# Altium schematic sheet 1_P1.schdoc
size 429 x 307 mm; Symbol: Drawing-Symbol_A4; Device: Drawing-Symbol_A4; Company: 嘉立创EDA; Version: V1.0; Page Size: A4; @Project Name: Dual_Motor_Driver_V3.1; @Page Count: 1; @Update Date: 2025-08-30; @Create Date: 2025-08-30; @Schematic Name: Motor_Driver; @Page No: 1; @Page Name: P1; @Create Time: 14:29:45; @Update Time: 15:29:46; Width: 1655; Height: 1170; Region Start: 1; X Region Count: 6; Y Region Count: 4; Blade Width: 10; Title Block Position: 3
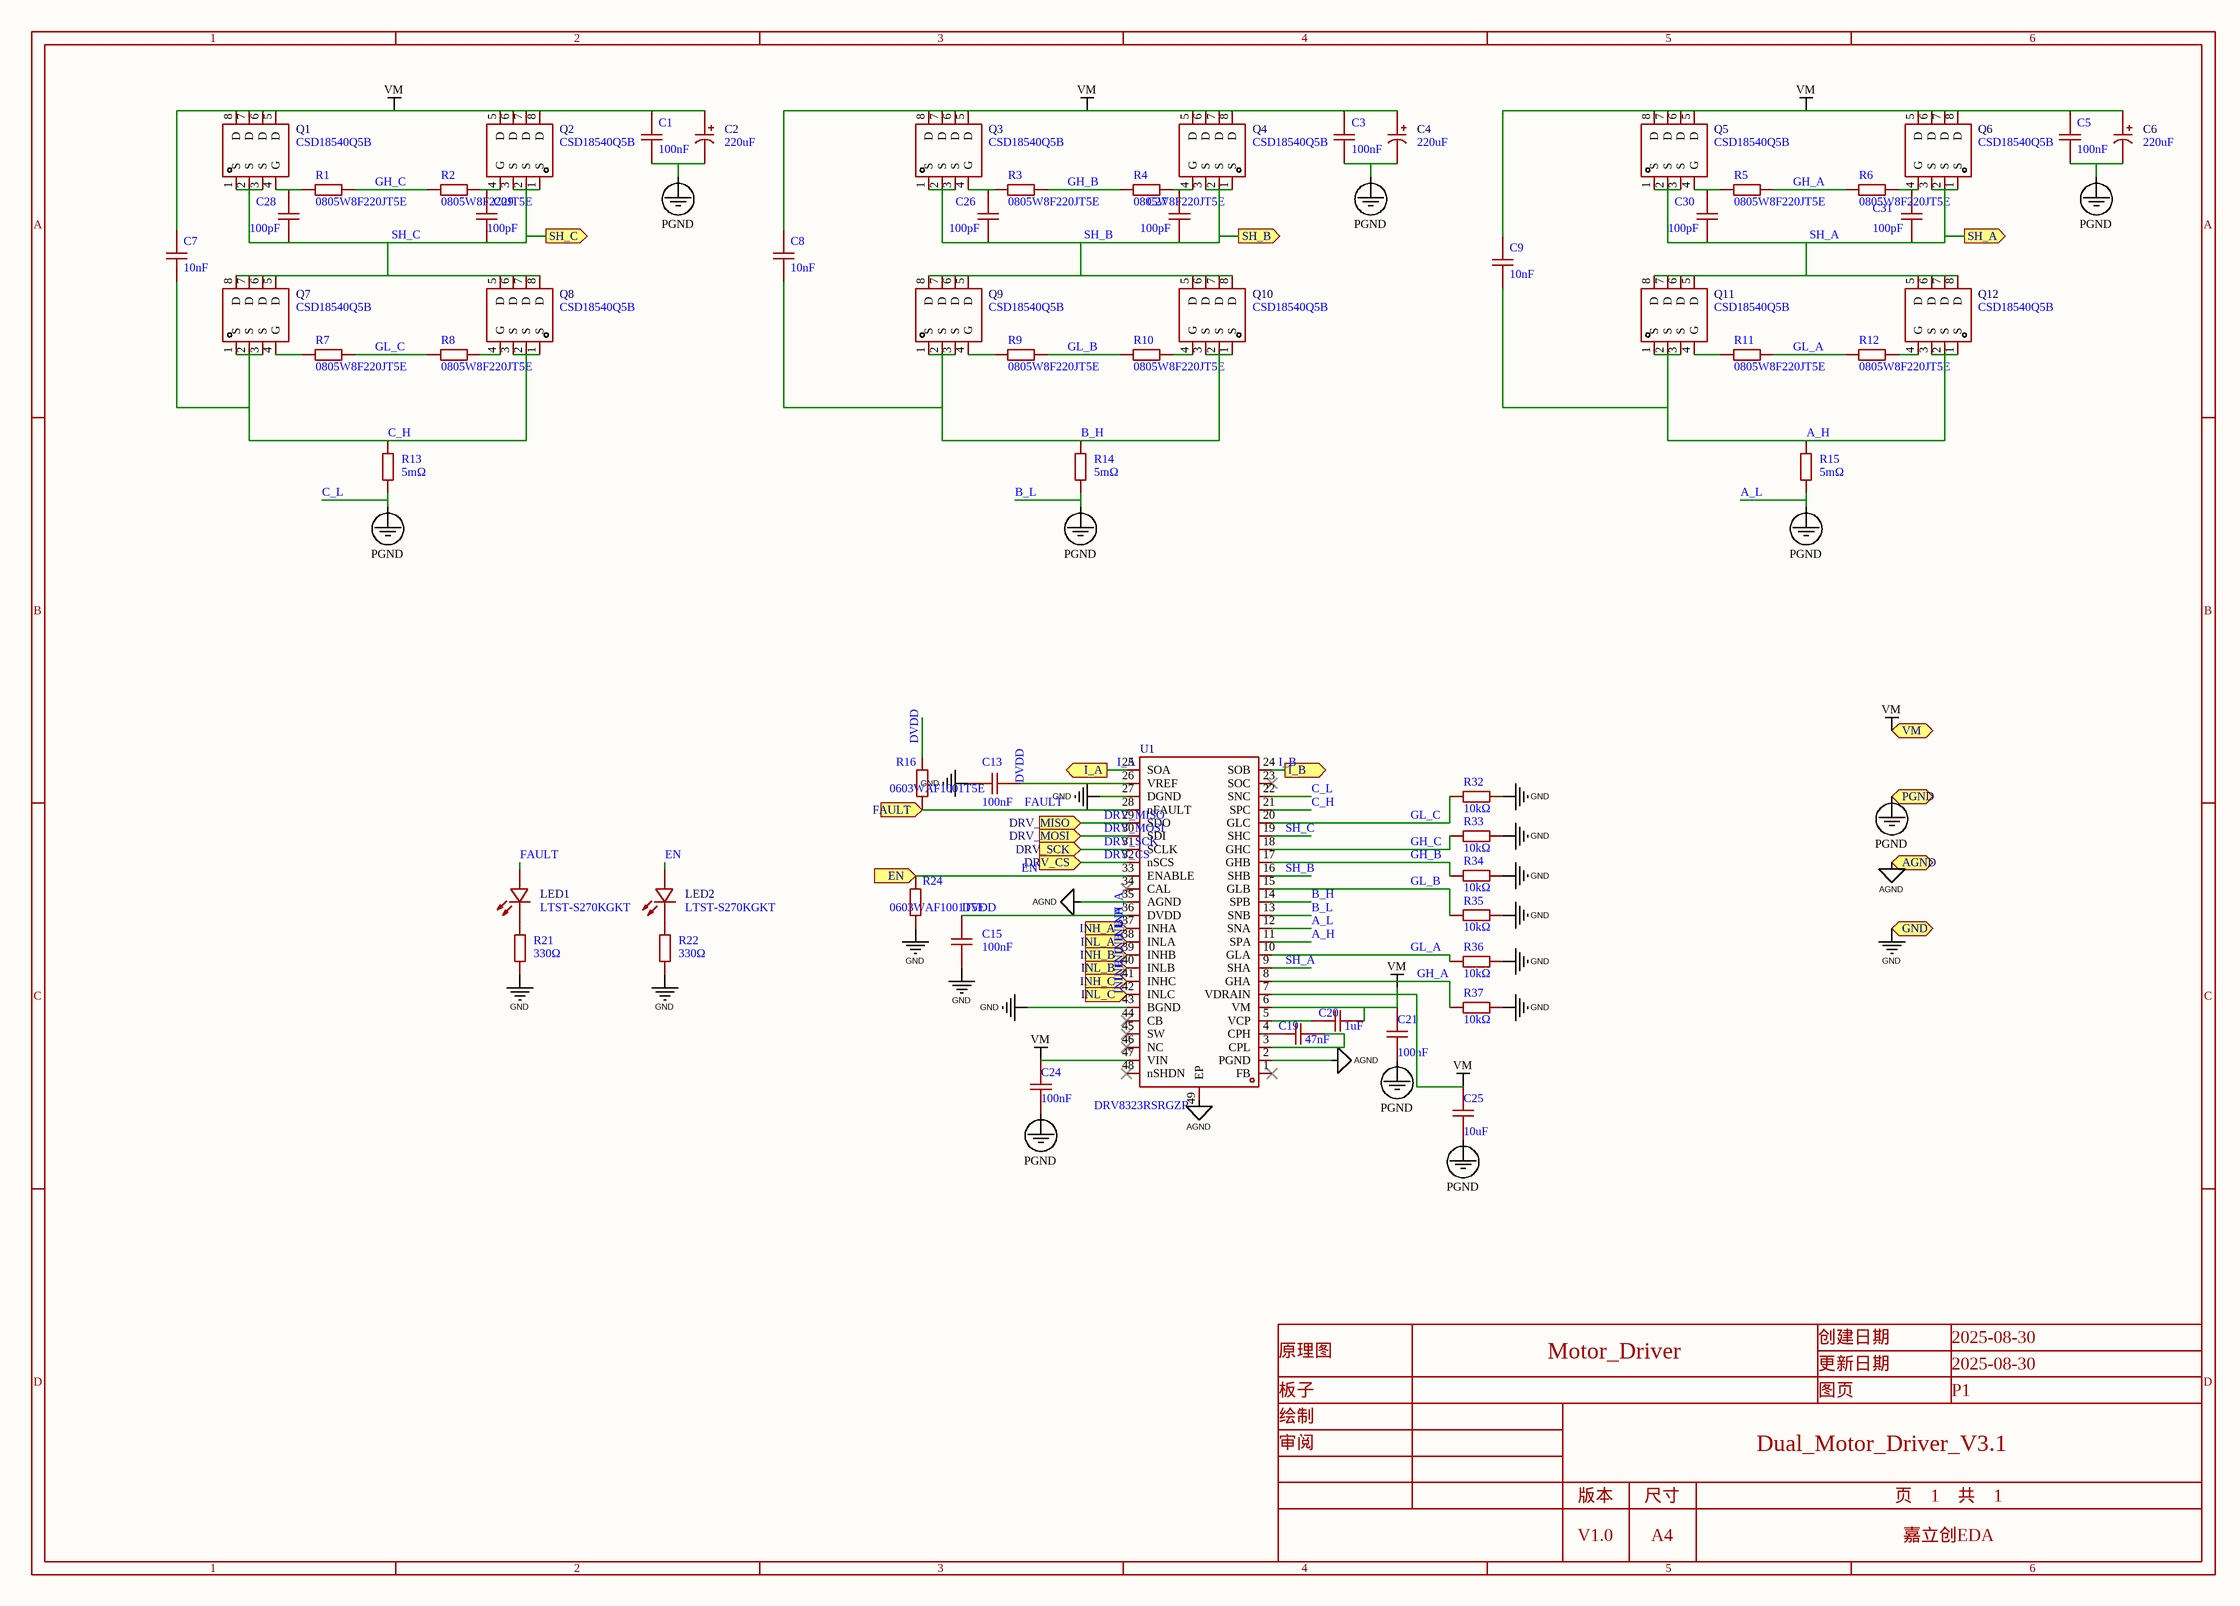
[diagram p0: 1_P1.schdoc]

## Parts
C1  100nF  [C1206]
C2  220uF  [CAP-SMD_BD12.5-L13.5-W13.5-FD-1]
C3  100nF  [C1206]
C4  220uF  [CAP-SMD_BD12.5-L13.5-W13.5-FD-1]
C5  100nF  [C1206]
C6  220uF  [CAP-SMD_BD12.5-L13.5-W13.5-FD-1]
C7  10nF  [C1206]
C8  10nF  [C1206]
C9  10nF  [C1206]
C13  100nF  [C0603]
C15  100nF  [C0603]
C19  47nF  [C0603]
C20  1uF  [C0805]
C21  100nF  [C0805]
C24  100nF  [C0805]
C25  10uF  [C0805]
C26  100pF  [C0603]
C27  100pF  [C0603]
C28  100pF  [C0603]
C29  100pF  [C0603]
C30  100pF  [C0603]
C31  100pF  [C0603]
LED1  LTST-S270KGKT  [LED-SMD_L1.7-W0.6-RD]
LED2  LTST-S270KGKT  [LED-SMD_L1.7-W0.6-RD]
Q1  CSD18540Q5B  [VSON-CLIP-8_L5.0-W6.0-P1.27-BL]
Q2  CSD18540Q5B  [VSON-CLIP-8_L5.0-W6.0-P1.27-BL]
Q3  CSD18540Q5B  [VSON-CLIP-8_L5.0-W6.0-P1.27-BL]
Q4  CSD18540Q5B  [VSON-CLIP-8_L5.0-W6.0-P1.27-BL]
Q5  CSD18540Q5B  [VSON-CLIP-8_L5.0-W6.0-P1.27-BL]
Q6  CSD18540Q5B  [VSON-CLIP-8_L5.0-W6.0-P1.27-BL]
Q7  CSD18540Q5B  [VSON-CLIP-8_L5.0-W6.0-P1.27-BL]
Q8  CSD18540Q5B  [VSON-CLIP-8_L5.0-W6.0-P1.27-BL]
Q9  CSD18540Q5B  [VSON-CLIP-8_L5.0-W6.0-P1.27-BL]
Q10  CSD18540Q5B  [VSON-CLIP-8_L5.0-W6.0-P1.27-BL]
Q11  CSD18540Q5B  [VSON-CLIP-8_L5.0-W6.0-P1.27-BL]
Q12  CSD18540Q5B  [VSON-CLIP-8_L5.0-W6.0-P1.27-BL]
R1  0805W8F220JT5E  [R0805]
R2  0805W8F220JT5E  [R0805]
R3  0805W8F220JT5E  [R0805]
R4  0805W8F220JT5E  [R0805]
R5  0805W8F220JT5E  [R0805]
R6  0805W8F220JT5E  [R0805]
R7  0805W8F220JT5E  [R0805]
R8  0805W8F220JT5E  [R0805]
R9  0805W8F220JT5E  [R0805]
R10  0805W8F220JT5E  [R0805]
R11  0805W8F220JT5E  [R0805]
R12  0805W8F220JT5E  [R0805]
R13  5mΩ  [R2512]
R14  5mΩ  [R2512]
R15  5mΩ  [R2512]
R16  0603WAF1001T5E  [R0603]
R21  330Ω  [R0603]
R22  330Ω  [R0603]
R24  0603WAF1001T5E  [R0603]
R32  10kΩ  [R0805]
R33  10kΩ  [R0805]
R34  10kΩ  [R0805]
R35  10kΩ  [R0805]
R36  10kΩ  [R0805]
R37  10kΩ  [R0805]
U1  DRV8323RSRGZR  [VQFN-48_L7.0-W7.0-P0.50-TL-EP5.1]

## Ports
AGND (bidir), DRV_CS (in), DRV_MISO (in), DRV_MOSI (in), DRV_SCK (in), EN (in), FAULT (in), GND (bidir), I_A (out), I_B (out), INH_A (in), INH_B (in), INH_C (in), INL_A (in), INL_B (in), INL_C (in), PGND (bidir), SH_A (out), SH_B (out), SH_C (out), VM (bidir)

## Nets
A_L: C1.1 C2.2 C3.1 C4.2 C5.1 C6.2 C21.2 C24.2 C25.2 R13.1 R14.1 R15.1 U1.12(SNA) U1.13(SNB) U1.22(SNC) ; port PGND  [also labelled B_L, C_L, PGND]
AGND: U1.2(PGND) U1.35(AGND) U1.49(EP) ; port AGND
GND: C13.1 C15.1 R21.1 R22.1 R24.1 R32.1 R33.1 R34.1 R35.1 R36.1 R37.1 U1.27(DGND) U1.43(BGND) ; port GND
VM: C1.2 C2.1 C3.2 C4.1 C5.2 C6.1 C7.2 C8.2 C9.2 C20.2 C21.1 C24.1 C25.1 Q1.5(D) Q1.6(D) Q1.7(D) Q1.8(D) Q2.5(D) Q2.6(D) Q2.7(D) Q2.8(D) Q3.5(D) Q3.6(D) Q3.7(D) Q3.8(D) Q4.5(D) Q4.6(D) Q4.7(D) Q4.8(D) Q5.5(D) Q5.6(D) Q5.7(D) Q5.8(D) Q6.5(D) Q6.6(D) Q6.7(D) Q6.8(D) U1.6(VM) U1.7(VDRAIN) U1.47(VIN) ; port VM
A_H: C9.1 Q11.1(S) Q11.2(S) Q11.3(S) Q12.1(S) Q12.2(S) Q12.3(S) R15.2 U1.11(SPA)
B_H: C8.1 Q9.1(S) Q9.2(S) Q9.3(S) Q10.1(S) Q10.2(S) Q10.3(S) R14.2 U1.14(SPB)
C_H: C7.1 Q7.1(S) Q7.2(S) Q7.3(S) Q8.1(S) Q8.2(S) Q8.3(S) R13.2 U1.21(SPC)
DRV_CS: U1.32(nSCS) ; port DRV_CS
DRV_MISO: U1.29(SDO) ; port DRV_MISO
DRV_MOSI: U1.30(SDI) ; port DRV_MOSI
DRV_SCK: U1.31(SCLK) ; port DRV_SCK
DVDD: C13.2 C15.2 R16.2 U1.26(VREF) U1.36(DVDD)
EN: LED2.2(A) R24.2 U1.33(ENABLE) ; port EN
FAULT: LED1.2(A) R16.1 U1.28(nFAULT) ; port FAULT
GH_A: R5.2 R6.1 R37.2 U1.8(GHA)
GH_B: R3.2 R4.1 R34.2 U1.17(GHB)
GH_C: R1.2 R2.1 R33.2 U1.18(GHC)
GL_A: R11.2 R12.1 R36.2 U1.10(GLA)
GL_B: R9.2 R10.1 R35.2 U1.15(GLB)
GL_C: R7.2 R8.1 R32.2 U1.20(GLC)
I_A: U1.25(SOA) ; port I_A
I_B: U1.24(SOB) ; port I_B
INH_A: U1.37(INHA) ; port INH_A
INH_B: U1.39(INHB) ; port INH_B
INH_C: U1.41(INHC) ; port INH_C
INL_A: U1.38(INLA) ; port INL_A
INL_B: U1.40(INLB) ; port INL_B
INL_C: U1.42(INLC) ; port INL_C
SH_A: C30.1 C31.1 Q5.1(S) Q5.2(S) Q5.3(S) Q6.1(S) Q6.2(S) Q6.3(S) Q11.5(D) Q11.6(D) Q11.7(D) Q11.8(D) Q12.5(D) Q12.6(D) Q12.7(D) Q12.8(D) U1.9(SHA) ; port SH_A
SH_B: C26.1 C27.1 Q3.1(S) Q3.2(S) Q3.3(S) Q4.1(S) Q4.2(S) Q4.3(S) Q9.5(D) Q9.6(D) Q9.7(D) Q9.8(D) Q10.5(D) Q10.6(D) Q10.7(D) Q10.8(D) U1.16(SHB) ; port SH_B
SH_C: C28.1 C29.1 Q1.1(S) Q1.2(S) Q1.3(S) Q2.1(S) Q2.2(S) Q2.3(S) Q7.5(D) Q7.6(D) Q7.7(D) Q7.8(D) Q8.5(D) Q8.6(D) Q8.7(D) Q8.8(D) U1.19(SHC) ; port SH_C
NetC19_1: C19.1 U1.4(CPH)
NetC19_2: C19.2 U1.3(CPL)
NetC20_1: C20.1 U1.5(VCP)
NetC26_2: C26.2 Q3.4(G) R3.1
NetC27_2: C27.2 Q4.4(G) R4.2
NetC28_2: C28.2 Q1.4(G) R1.1
NetC29_2: C29.2 Q2.4(G) R2.2
NetC30_2: C30.2 Q5.4(G) R5.1
NetC31_2: C31.2 Q6.4(G) R6.2
NetLED1_1: LED1.1(K) R21.2
NetLED2_1: LED2.1(K) R22.2
NetQ7_4: Q7.4(G) R7.1
NetQ8_4: Q8.4(G) R8.2
NetQ9_4: Q9.4(G) R9.1
NetQ10_4: Q10.4(G) R10.2
NetQ11_4: Q11.4(G) R11.1
NetQ12_4: Q12.4(G) R12.2

Not connected (* = marked no-connect by the designer): U1 1(FB)* 23(SOC)* 34(CAL)* 44(CB)* 45(SW)* 46(NC)* 48(nSHDN)*

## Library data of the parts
C1 C3 C5 = CL31B104KBCNNNC: Manufacturer: SAMSUNG(三星); Symbol: Capacitance; Add into BOM: yes; Tolerance: ±10%; Voltage Rated: 50V; Temperature Coefficient: X7R
C2 C4 C6 = VMML1652A221MV: Manufacturer: Ymin(永铭); Add into BOM: yes; Tolerance: ±20%; Rated Voltage: 100V; Reuse Block: Motor Driver
C7-C9 = CC1206KRX7R0BB103: Manufacturer: YAGEO(国巨); Symbol: Capacitance; Add into BOM: yes; Tolerance: ±10%; Voltage Rated: 100V; Temperature Coefficient: X7R
C13 C15 = CL10B104KC8NNNC: Manufacturer: SAMSUNG(三星); Symbol: Capacitance; Add into BOM: yes; Tolerance: ±10%; Voltage Rated: 100V; Temperature Coefficient: X7R; Reuse Block: Motor Driver
C19 = AC0603KRX7R0BB473: Manufacturer: YAGEO(国巨); Symbol: Capacitance; Add into BOM: yes; Tolerance: ±10%; Voltage Rated: 100V; Temperature Coefficient: X7R; Reuse Block: Motor Driver
C20 = GCM21BC72A105KE36L: Manufacturer: muRata(村田); Symbol: Capacitance; Add into BOM: yes; Tolerance: ±10%; Voltage Rated: 100V; Temperature Coefficient: X7S; Reuse Block: Motor Driver
C21 = CL21B104KCFNNNE: Manufacturer: SAMSUNG(三星); Symbol: Capacitance; Add into BOM: yes; Tolerance: ±10%; Voltage Rated: 100V; Temperature Coefficient: X7R; Reuse Block: Motor Driver
C24 = GCM21BR72A104KA37L: Manufacturer: muRata(村田); Symbol: Capacitance; Add into BOM: yes; Tolerance: ±10%; Voltage Rated: 100V; Temperature Coefficient: X7R; Reuse Block: Motor Driver
C25 = CL21A106KAYNNNE_C15850: Manufacturer: SAMSUNG(三星); Symbol: Capacitance; Add into BOM: yes; Tolerance: ±10%; Voltage Rated: 25V; Temperature Coefficient: X5R
C26-C31 = CL10C101JB8NNNC: Manufacturer: SAMSUNG(三星); Symbol: Capacitance; Add into BOM: yes; Tolerance: ±5%; Voltage Rated: 50V; Temperature Coefficient: C0G
LED1 LED2 = LTST-S270KGKT: Manufacturer: LITEON(光宝); Add into BOM: yes; Emitted Color: 黄绿色; Power Dissipation: 75mW; Forward Current: 20mA; Dominant Wavelength: 571nm; Peak Wavelength: 574nm; Lens Color: 无色透明透镜; Viewing Angle: 130°; Mounting Sytle: 侧贴
Q1-Q12 = CSD18540Q5B: Manufacturer: TI(德州仪器); Add into BOM: yes; Type: 1个N沟道; Drain Source Voltage (Vdss): 60V; Continuous Drain Current (Id): 205A; Drain Source On Resistance (RDS(on)@Vgs,Id): 2.6mΩ@10V,28A; Power Dissipation (Pd): 3.8W; Gate Threshold Voltage (Vgs(th)@Id): 1.9V@250uA; Total Gate Charge (Qg@Vgs): 41nC@10V; Input Capacitance (Ciss@Vds): 4.23nF@30V; Reverse Transfer Capacitance (Crss@Vds): 20pF@30V; Reuse Block: Motor Driver
R1-R12 = 0805W8F220JT5E: Manufacturer: UNI-ROYAL(厚声); Symbol: 电阻; Add into BOM: yes
R13-R15 = HoYLR2512-2W-5mR-1%: Manufacturer: Milliohm(毫欧); Symbol: 电阻; Add into BOM: yes; Tolerance: ±1%; Power(Watts): 2W; Mounting Sytle: 贴片; Reuse Block: Motor Driver
R16 R24 = 0603WAF1001T5E: Manufacturer: UNI-ROYAL(厚声); Symbol: 电阻; Add into BOM: yes
R21 R22 = 0603WAF3300T5E: Manufacturer: UNI-ROYAL(厚声); Symbol: 电阻; Add into BOM: yes; Tolerance: ±1%; Power(Watts): 100mW; Overload Voltage (Max): 75V; Temperature Coefficient: ±100ppm/℃
R32-R37 = 0805W8F1002T5E_C17414: Manufacturer: UNI-ROYAL(厚声); Symbol: 电阻; Add into BOM: yes; Tolerance: ±1%; Power(Watts): 125mW; Overload Voltage (Max): 150V; Temperature Coefficient: ±100ppm/℃; Reuse Block: Motor Driver
U1 = DRV8323RSRGZR: Manufacturer: TI(德州仪器); Add into BOM: yes; Reuse Block: Motor Driver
